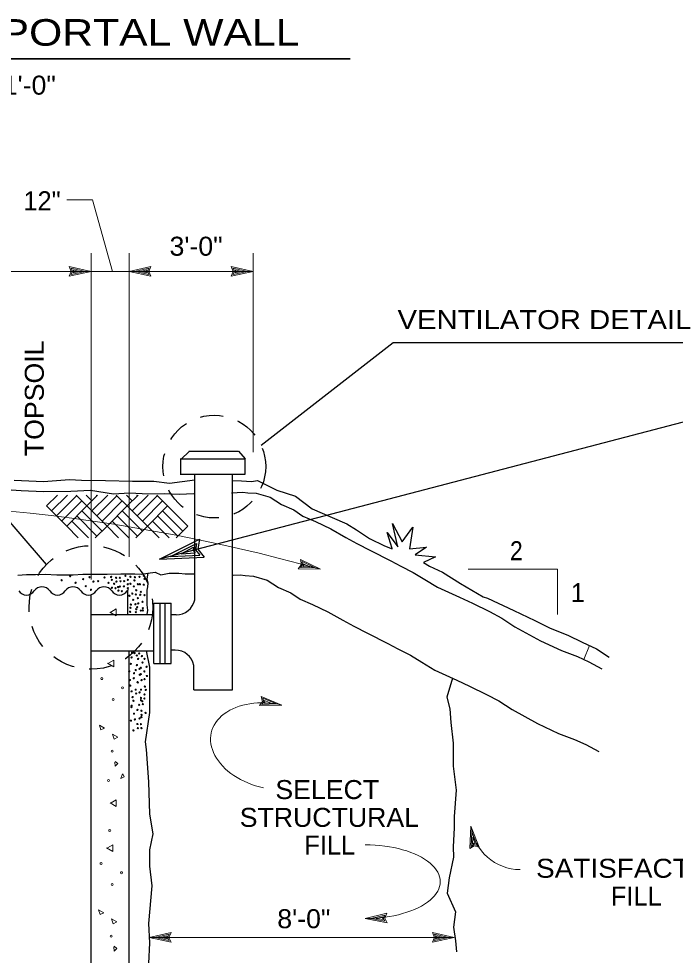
# Model space of a CAD drawing. Extents: x -22.3 to 19.7, y -11.8 to 18.2.
# Drawn here: x -4.47 to -0.15, y -6.32 to -0.16 of the extents above; entities that cross this region are included whole.
import ezdxf
from ezdxf.enums import TextEntityAlignment as Align

# ---------------------------------------------------------------- set-up
doc = ezdxf.new("R2010")
doc.units = 0
doc.header["$LTSCALE"] = 0.05
doc.linetypes.add('MEDIUM_DASHED', pattern=[4.5, 3, -1.5])
doc.layers.add('1', color=7, linetype='Continuous', lineweight=13)
doc.layers.add('2', color=7, linetype='Continuous', lineweight=13)

msp = doc.modelspace()

# ---------------------------------------------------------------- linework, layer by layer
at = {"layer": '1', "lineweight": 35}
msp.add_line((-7.37642, -0.42569), (-2.28642, -0.42569), dxfattribs=at)
at = {"layer": '1'}
for p, q in [((-3.99142, -3.85069), (-3.99142, -1.70369)), ((-3.74142, -3.70269), (-3.74142, -1.70369)), ((-2.92542, -3.01369), (-2.92542, -1.70369)), ((-8.41542, -1.82369), (-3.99142, -1.82369)), ((-3.99142, -1.82369), (-4.13542, -1.79269)), ((-3.99142, -1.82369), (-4.13542, -1.85469)), ((-4.02842, -1.82369), (-4.12242, -1.80369)), ((-4.11342, -1.82369), (-4.12242, -1.80369)), ((-4.02842, -1.82369), (-4.12242, -1.84369)), ((-4.12242, -1.84369), (-4.11342, -1.82369)), ((-4.06442, -1.82369), (-4.10942, -1.81469)), ((-4.10542, -1.82369), (-4.10942, -1.81469)), ((-4.06442, -1.82369), (-4.10942, -1.83369)), ((-4.10942, -1.83369), (-4.10542, -1.82369)), ((-3.74142, -1.82369), (-3.59742, -1.79269)), ((-3.74142, -1.82369), (-3.59742, -1.85469)), ((-3.70442, -1.82369), (-3.61042, -1.80369)), ((-3.70442, -1.82369), (-3.61042, -1.84369)), ((-3.66842, -1.82369), (-3.62342, -1.81369)), ((-3.66842, -1.82369), (-3.62342, -1.83269)), ((-3.62342, -1.81369), (-3.62742, -1.82369)), ((-3.62742, -1.82369), (-3.62342, -1.83269)), ((-3.61042, -1.80369), (-3.61942, -1.82369)), ((-3.61942, -1.82369), (-3.61042, -1.84369)), ((-2.92542, -1.82369), (-3.06942, -1.79269)), ((-2.92542, -1.82369), (-3.06942, -1.85469)), ((-2.96242, -1.82369), (-3.05642, -1.80369)), ((-3.04742, -1.82369), (-3.05642, -1.80369)), ((-2.96242, -1.82369), (-3.05642, -1.84369)), ((-3.05642, -1.84369), (-3.04742, -1.82369)), ((-2.99842, -1.82369), (-3.04342, -1.81469)), ((-3.03942, -1.82369), (-3.04342, -1.81469)), ((-2.99842, -1.82369), (-3.04342, -1.83369)), ((-3.04342, -1.83369), (-3.03942, -1.82369)), ((-4.28442, -3.36669), (-4.21342, -3.29569)), ((-4.25142, -3.40069), (-4.14742, -3.29569)), ((-4.21842, -3.43369), (-4.08542, -3.29969)), ((-4.01942, -3.36669), (-4.09042, -3.29569)), ((-3.98642, -3.33369), (-4.02442, -3.29569)), ((-4.01942, -3.36669), (-3.94842, -3.29569)), ((-4.01942, -3.36669), (-3.94842, -3.29569)), ((-3.98642, -3.40069), (-3.88142, -3.29569)), ((-3.95342, -3.29969), (-3.95742, -3.29569)), ((-3.95342, -3.43369), (-3.82042, -3.29969)), ((-3.75342, -3.36669), (-3.82542, -3.29569)), ((-3.72042, -3.33369), (-3.75842, -3.29569)), ((-3.75342, -3.36669), (-3.68242, -3.29569)), ((-3.72042, -3.40069), (-3.61542, -3.29569)), ((-3.68742, -3.29969), (-3.69142, -3.29569)), ((-3.68742, -3.43369), (-3.55442, -3.29969)), ((-3.48842, -3.36669), (-3.55942, -3.29569)), ((-4.18542, -3.46669), (-4.05242, -3.33369)), ((-4.15142, -3.49969), (-4.01942, -3.36669)), ((-3.88642, -3.49969), (-4.01942, -3.36669)), ((-3.91942, -3.46669), (-3.78742, -3.33369)), ((-3.88642, -3.49969), (-3.75342, -3.36669)), ((-3.65342, -3.46669), (-3.52142, -3.33369)), ((-3.62042, -3.49969), (-3.48842, -3.36669)), ((-3.35542, -3.49969), (-3.48842, -3.36669)), ((-3.95342, -3.56569), (-4.08542, -3.43369)), ((-3.91942, -3.53269), (-4.05242, -3.40069)), ((-3.68642, -3.56569), (-3.82042, -3.43369)), ((-3.65342, -3.53269), (-3.78742, -3.40069)), ((-3.42142, -3.56569), (-3.55442, -3.43369)), ((-3.38842, -3.53269), (-3.52142, -3.40069)), ((-4.00942, -3.57669), (-4.11842, -3.46669)), ((-3.96342, -3.57669), (-3.88642, -3.49969)), ((-3.81042, -3.57669), (-3.88642, -3.49969)), ((-3.74242, -3.57669), (-3.85342, -3.46669)), ((-3.69742, -3.57669), (-3.62042, -3.49969)), ((-3.47742, -3.57669), (-3.58742, -3.46669)), ((-3.43242, -3.57669), (-3.35542, -3.49969)), ((-2.48142, -3.78469), (-2.61342, -3.72069)), ((-2.61342, -3.77269), (-2.59942, -3.75569)), ((-2.51742, -3.77569), (-2.60342, -3.73369)), ((-2.59942, -3.75569), (-2.60342, -3.73369)), ((-2.59842, -3.76669), (-2.59242, -3.75769)), ((-2.55242, -3.76769), (-2.59342, -3.74769)), ((-2.59242, -3.75769), (-2.59342, -3.74769)), ((-2.48142, -3.78469), (-2.62842, -3.78069)), ((-2.51742, -3.77569), (-2.61342, -3.77269)), ((-2.55242, -3.76769), (-2.59842, -3.76669)), ((-0.74842, -4.37869), (-0.71142, -4.28669)), ((-2.73542, -4.67769), (-2.87142, -4.62069)), ((-2.73542, -4.67769), (-2.88242, -4.68169)), ((-2.86742, -4.67369), (-2.85542, -4.65569)), ((-2.77142, -4.67069), (-2.86742, -4.67369)), ((-2.77142, -4.67069), (-2.86042, -4.63369)), ((-2.85542, -4.65569), (-2.86042, -4.63369)), ((-2.85342, -4.66569), (-2.84742, -4.65669)), ((-2.80742, -4.66469), (-2.85342, -4.66569)), ((-2.80742, -4.66469), (-2.84942, -4.64769)), ((-2.84742, -4.65669), (-2.84942, -4.64769)), ((-1.49242, -5.47569), (-1.49942, -5.62269)), ((-1.49242, -5.47569), (-1.43842, -5.61269)), ((-1.48642, -5.51169), (-1.49042, -5.60869)), ((-1.48642, -5.51169), (-1.45142, -5.60169)), ((-1.47242, -5.59569), (-1.49042, -5.60869)), ((-1.48042, -5.54769), (-1.48142, -5.59369)), ((-1.47342, -5.58769), (-1.48142, -5.59369)), ((-1.48042, -5.54769), (-1.46342, -5.59069)), ((-1.46342, -5.59069), (-1.47342, -5.58769)), ((-1.45142, -5.60169), (-1.47242, -5.59569)), ((-2.18842, -6.08269), (-2.04542, -6.04869)), ((-2.18842, -6.08269), (-2.04342, -6.11069)), ((-2.15142, -6.08169), (-2.05742, -6.05969)), ((-2.15142, -6.08169), (-2.05742, -6.09969)), ((-2.11542, -6.08169), (-2.07042, -6.07069)), ((-2.11542, -6.08169), (-2.07042, -6.08969)), ((-2.07042, -6.07069), (-2.07442, -6.08069)), ((-2.07442, -6.08069), (-2.07042, -6.08969)), ((-2.05742, -6.05969), (-2.06642, -6.08069)), ((-2.06642, -6.08069), (-2.05742, -6.09969)), ((-3.60942, -6.20669), (-3.46542, -6.17569)), ((-3.60942, -6.20669), (-1.60142, -6.20669)), ((-3.60942, -6.20669), (-3.46542, -6.23769)), ((-3.57242, -6.20669), (-3.47842, -6.18669)), ((-3.57242, -6.20669), (-3.47842, -6.22669)), ((-3.53642, -6.20669), (-3.49142, -6.19669)), ((-3.53642, -6.20669), (-3.49142, -6.21569)), ((-3.49142, -6.19669), (-3.49542, -6.20669)), ((-3.49542, -6.20669), (-3.49142, -6.21569)), ((-3.47842, -6.18669), (-3.48742, -6.20669)), ((-3.48742, -6.20669), (-3.47842, -6.22669)), ((-1.60142, -6.20669), (-1.74542, -6.17569)), ((-1.60142, -6.20669), (-1.74542, -6.23769)), ((-1.63842, -6.20669), (-1.73242, -6.18669)), ((-1.72342, -6.20669), (-1.73242, -6.18669)), ((-1.63842, -6.20669), (-1.73242, -6.22669)), ((-1.73242, -6.22669), (-1.72342, -6.20669)), ((-1.67442, -6.20669), (-1.71942, -6.19769)), ((-1.71542, -6.20669), (-1.71942, -6.19769)), ((-1.67442, -6.20669), (-1.71942, -6.21669)), ((-1.71942, -6.21669), (-1.71542, -6.20669))]:
    msp.add_line(p, q, dxfattribs=at)
at = {"layer": '1', "lineweight": 25}
for p, q in [((-2.00442, -2.29469), (-2.87242, -2.96869)), ((-0.01042, -2.29469), (-2.00442, -2.29469)), ((-3.40142, -3.06269), (-3.34442, -3.00669)), ((-3.34842, -3.00669), (-3.02142, -3.00669)), ((-3.02142, -3.00669), (-2.97742, -3.05769)), ((-3.40542, -3.05769), (-2.97742, -3.05769)), ((-3.40142, -3.16369), (-3.40142, -3.06269)), ((-2.97742, -3.15869), (-2.97742, -3.05769)), ((-3.40242, -3.15869), (-2.97742, -3.15869)), ((-3.30942, -3.98469), (-3.30942, -3.16169)), ((-3.06142, -4.57769), (-3.06142, -3.15869)), ((-3.46842, -3.69969), (-3.29742, -3.61369)), ((-3.29742, -3.61369), (-3.30442, -3.65669)), ((-3.46842, -3.69969), (-3.27642, -3.69069)), ((-3.39942, -3.68169), (-3.31742, -3.63969)), ((-3.39942, -3.68169), (-3.30742, -3.67669)), ((-3.31742, -3.63969), (-3.31942, -3.66069)), ((-3.31942, -3.66069), (-3.30742, -3.67669)), ((-3.30442, -3.65669), (-3.27642, -3.69069)), ((-3.54042, -3.71869), (-3.24642, -3.70569)), ((-3.75042, -4.08169), (-3.75042, -3.91869)), ((-3.99142, -7.93169), (-3.99142, -3.95369)), ((-3.57942, -4.40369), (-3.57942, -4.00769)), ((-3.57942, -4.00769), (-3.46542, -4.00769)), ((-3.53742, -4.40369), (-3.53742, -4.00769)), ((-3.50442, -4.40369), (-3.50442, -4.00769)), ((-3.46542, -4.40369), (-3.46542, -4.00769)), ((-3.99142, -4.08169), (-3.57942, -4.08169)), ((-3.43242, -4.08469), (-3.46542, -4.08469)), ((-3.99142, -4.32169), (-3.57942, -4.32169)), ((-3.74142, -7.93169), (-3.74142, -4.32169)), ((-3.43742, -4.31669), (-3.46542, -4.31669)), ((-3.57942, -4.40369), (-3.46542, -4.40369)), ((-3.31442, -4.57769), (-3.31442, -4.41669)), ((-3.31442, -4.57769), (-3.06142, -4.57769))]:
    msp.add_line(p, q, dxfattribs=at)
at = {"layer": '1'}
for points in [[(-3.85142, -1.82369), (-3.98242, -1.35269), (-4.15142, -1.35269)], [(-4.13542, -1.85469), (-4.12142, -1.82369), (-4.13542, -1.79269)], [(-3.99142, -1.82369), (-3.74142, -1.82369), (-2.92542, -1.82369)], [(-3.59742, -1.79269), (-3.61142, -1.82369), (-3.59742, -1.85469)], [(-3.06942, -1.85469), (-3.05542, -1.82369), (-3.06942, -1.79269)], [(-3.54442, -3.57669), (-3.75342, -3.36669), (-3.68242, -3.29569)], [(-4.07542, -3.57669), (-4.15142, -3.49969), (-4.28442, -3.36669)], [(-2.62842, -3.78069), (-2.60742, -3.75369), (-2.61342, -3.72069)], [(-1.50942, -3.78469), (-0.92142, -3.78469), (-0.92142, -4.08269)], [(-2.88242, -4.68169), (-2.86342, -4.65369), (-2.87142, -4.62069)], [(-1.43842, -5.61269), (-1.47142, -5.60369), (-1.49942, -5.62269)], [(-2.04542, -6.04869), (-2.05842, -6.08069), (-2.04342, -6.11069)], [(-3.46542, -6.17569), (-3.47942, -6.20669), (-3.46542, -6.23769)], [(-1.74542, -6.23769), (-1.73142, -6.20669), (-1.74542, -6.17569)]]:
    msp.add_lwpolyline(points, dxfattribs=at)
at = {"layer": '1', "lineweight": 25}
for points in [[(-6.26642, -2.32569), (-5.51542, -2.32569), (-4.28642, -3.75369)], [(1.92558, -2.28769), (-3.54042, -3.71869), (-3.27742, -3.58569)], [(-4.49642, -3.19769), (-4.30442, -3.20569), (-4.13442, -3.19369), (-4.05342, -3.19869), (-3.89642, -3.20069), (-3.71942, -3.20369), (-3.57842, -3.20369), (-3.47642, -3.21669), (-3.30942, -3.19569)], [(-3.06042, -3.19969), (-3.00242, -3.20169), (-2.93542, -3.20669), (-2.89642, -3.20069), (-2.76942, -3.26269), (-2.64542, -3.30369), (-2.53742, -3.38569), (-2.40442, -3.44469), (-2.30942, -3.48569), (-2.24542, -3.52569), (-2.15942, -3.58269), (-2.06142, -3.62969), (-2.01042, -3.64969), (-2.01042, -3.64869), (-2.04342, -3.54269), (-1.97342, -3.63669), (-2.00842, -3.48369), (-1.94542, -3.60269), (-1.87442, -3.50669), (-1.89642, -3.65069), (-1.78342, -3.63969), (-1.85842, -3.68969), (-1.72542, -3.70269), (-1.80442, -3.73869), (-1.76442, -3.76369), (-1.67942, -3.80269), (-1.56042, -3.87869), (-1.41142, -3.96469), (-1.38342, -3.97469), (-1.21042, -4.05569), (-1.07242, -4.12169), (-0.97142, -4.17169), (-0.85442, -4.21869), (-0.75942, -4.26469), (-0.66642, -4.30769), (-0.58242, -4.36369)], [(-7.18642, -3.26769), (-6.94542, -3.26969), (-6.68842, -3.26469), (-6.47842, -3.26069), (-6.30242, -3.27369), (-6.14842, -3.27069), (-5.85542, -3.27169), (-5.57142, -3.26469), (-5.41742, -3.26569), (-5.22942, -3.26569), (-5.00642, -3.25869), (-4.78642, -3.24969), (-4.61642, -3.25469), (-4.45142, -3.26569), (-4.30442, -3.27269), (-4.12542, -3.27069), (-3.99542, -3.26469), (-3.84342, -3.28769), (-3.73842, -3.28069), (-3.61442, -3.28869), (-3.50942, -3.28469), (-3.41242, -3.29069), (-3.31442, -3.28569)], [(-3.06742, -3.28069), (-2.99242, -3.27669), (-2.95942, -3.28069), (-2.90442, -3.28369), (-2.81342, -3.31069), (-2.73842, -3.35869), (-2.65742, -3.39369), (-2.59742, -3.43569), (-2.51542, -3.47069), (-2.41342, -3.51869), (-2.31542, -3.57469), (-2.24242, -3.61469), (-2.15242, -3.66069), (-2.01942, -3.72869), (-1.95342, -3.76369), (-1.87142, -3.80469), (-1.79542, -3.85169), (-1.71142, -3.90269), (-1.56642, -3.96869), (-1.48142, -4.00769), (-1.36942, -4.06269), (-1.28942, -4.10569), (-1.20242, -4.16269), (-1.03442, -4.25469), (-0.89642, -4.31969), (-0.79142, -4.35869), (-0.71642, -4.39269), (-0.63142, -4.43869)], [(-3.27742, -3.58569), (-3.28842, -3.65269), (-3.24642, -3.70569)], [(-4.47242, -3.82369), (-4.41542, -3.81869), (-4.35642, -3.81869), (-4.29242, -3.81569), (-4.21742, -3.82069), (-4.17342, -3.82069), (-4.10942, -3.82069), (-4.04542, -3.81569), (-3.96642, -3.81569), (-3.88542, -3.81569), (-3.79642, -3.81369), (-3.70342, -3.81369), (-3.65742, -3.81569), (-3.61842, -3.80969), (-3.62342, -3.84769), (-3.61842, -3.87369), (-3.61942, -3.90069), (-3.62342, -3.92169), (-3.62342, -3.96969), (-3.62342, -4.00769), (-3.62542, -4.01769), (-3.61942, -4.05369), (-3.62342, -4.08169)], [(-3.61842, -3.80969), (-3.57042, -3.80369), (-3.53142, -3.82169), (-3.47742, -3.81069), (-3.41342, -3.81069), (-3.37142, -3.81469), (-3.30942, -3.81469)], [(-3.05742, -3.82369), (-3.01142, -3.82169), (-2.97842, -3.82569), (-2.92342, -3.82869), (-2.83242, -3.85569), (-2.75742, -3.90369), (-2.67642, -3.93869), (-2.61642, -3.98069), (-2.53442, -4.01569), (-2.43242, -4.06369), (-2.33442, -4.11969), (-2.26142, -4.15969), (-2.17142, -4.20569), (-2.03842, -4.27369), (-1.97242, -4.30869), (-1.89042, -4.34969), (-1.81442, -4.39669), (-1.73042, -4.44769), (-1.58542, -4.51369), (-1.50042, -4.55269), (-1.38842, -4.60769), (-1.30842, -4.65069), (-1.22142, -4.70769), (-1.05342, -4.79969), (-0.91542, -4.86469), (-0.81042, -4.90369), (-0.73542, -4.93769), (-0.65042, -4.98369)], [(-3.62842, -4.32169), (-3.60742, -4.42869), (-3.60742, -4.52069), (-3.60742, -4.62769), (-3.60742, -4.72769), (-3.63542, -4.91969), (-3.62842, -4.96969), (-3.61442, -5.18269), (-3.60742, -5.39669), (-3.58542, -5.52469), (-3.60742, -5.63169), (-3.60742, -5.73869), (-3.59242, -5.86669), (-3.61442, -6.11569), (-3.60742, -6.24369), (-3.61442, -6.37869)], [(-1.61342, -4.50069), (-1.65042, -4.62669), (-1.63042, -4.70269), (-1.62342, -4.79169), (-1.60942, -4.92969), (-1.60942, -5.08069), (-1.58842, -5.23869), (-1.60242, -5.41069), (-1.60242, -5.48669), (-1.60942, -5.61069)], [(-1.60942, -5.61069), (-1.60742, -5.67969), (-1.63442, -5.81469), (-1.64842, -5.91669), (-1.59342, -6.03869), (-1.60742, -6.13969), (-1.59342, -6.22869), (-1.58742, -6.30269)]]:
    msp.add_lwpolyline(points, dxfattribs=at)
at = {"layer": '1', "linetype": 'MEDIUM_DASHED', "lineweight": 25}
for centre, radius in [((-3.18042, -3.10869), 0.338), ((-3.99242, -4.03569), 0.40702)]:
    msp.add_circle(centre, radius, dxfattribs=at)
at = {"layer": '1'}
for centre in [(-4.18492, -3.85669), (-4.12892, -3.83069), (-4.09292, -3.87269), (-4.04392, -3.84969), (-4.00192, -3.83669), (-3.97592, -3.86569), (-3.94492, -3.86269), (-3.90292, -3.83769), (-3.87692, -3.87369), (-3.85992, -3.83469), (-3.85392, -3.85369), (-3.83992, -3.87969), (-3.82692, -3.83969), (-3.82492, -3.86569), (-3.80192, -3.83969), (-3.79792, -3.86369), (-3.77292, -3.86269), (-3.76592, -3.82769), (-3.74992, -3.88269), (-3.74892, -3.85369), (-3.73292, -3.83369), (-3.73292, -3.87969), (-3.70592, -3.85769), (-3.70292, -3.83669), (-3.68292, -3.88269), (-3.67292, -3.83469), (-3.66992, -3.88269), (-3.64492, -3.82769), (-3.64492, -3.88569), (-3.63992, -3.84669), (-4.02692, -3.89569), (-3.99192, -3.91869), (-3.85392, -3.90569), (-3.83092, -3.90969), (-3.81392, -3.90169), (-3.81192, -3.92469), (-3.80192, -3.89869), (-3.78892, -3.92869), (-3.77492, -3.89669), (-3.74992, -3.90869), (-3.71992, -3.94469), (-3.70992, -3.89669), (-3.69392, -3.92269), (-3.66392, -3.93269), (-3.73892, -3.95869), (-3.71392, -3.98569), (-3.69692, -3.94969), (-3.68292, -3.97469), (-3.68092, -4.00869), (-3.66792, -3.95169), (-3.65292, -3.99769), (-3.63992, -3.95469), (-3.73492, -4.06369), (-3.73292, -4.03769), (-3.72892, -4.01669), (-3.69992, -4.01469), (-3.69692, -4.06669), (-3.69392, -4.04769), (-3.68892, -4.03369), (-3.66392, -4.05669), (-3.65092, -4.04069), (-3.65092, -4.05469), (-3.72492, -4.36469), (-3.72192, -4.33369), (-3.70492, -4.33569), (-3.69092, -4.35169), (-3.68192, -4.37469), (-3.67492, -4.33769), (-3.65692, -4.35569), (-3.63992, -4.37469), (-3.72892, -4.40669), (-3.68992, -4.41469), (-3.67192, -4.43969), (-3.66392, -4.43269), (-3.65292, -4.39869), (-3.62592, -4.42569), (-3.73992, -4.45669), (-3.71092, -4.50169), (-3.70892, -4.46869), (-3.69792, -4.44769), (-3.67092, -4.47869), (-3.66292, -4.47469), (-3.64092, -4.45669), (-3.62392, -4.48669), (-3.73592, -4.51369), (-3.73392, -4.54969), (-3.68592, -4.52669), (-3.68392, -4.52969), (-3.65892, -4.51369), (-3.63992, -4.50669), (-3.63692, -4.55669), (-3.72492, -4.58769), (-3.71792, -4.62569), (-3.69792, -4.57669), (-3.69492, -4.60169), (-3.67192, -4.59469), (-3.66292, -4.57669), (-3.63992, -4.60769), (-3.63192, -4.57869), (-3.72492, -4.68269), (-3.71292, -4.64969), (-3.67492, -4.67669), (-3.66292, -4.63069), (-3.66292, -4.64569), (-3.65492, -4.65269), (-3.65092, -4.67169), (-3.64092, -4.63469), (-3.72592, -4.69169), (-3.70892, -4.73469), (-3.68692, -4.70969), (-3.65992, -4.71569), (-3.65892, -4.74269), (-3.63292, -4.72969), (-3.72892, -4.78069), (-3.70292, -4.77269), (-3.68692, -4.80269), (-3.67192, -4.76569), (-3.66292, -4.80369), (-3.65992, -4.75669), (-3.71292, -4.84469), (-3.68392, -4.82969), (-3.65992, -4.82969)]:
    msp.add_circle(centre, 0.0043, dxfattribs=at)
for centre, radius, start, end in [((-5.65272, -15.07871), 11.73082, 74.31555, 96.07119), ((-1.16652, -5.43185), 0.32884, 187.66046, 269.843)]:
    msp.add_arc(centre, radius, start, end, dxfattribs=at)
at = {"layer": '1', "lineweight": 25}
for centre, radius, start, end in [((-4.41642, -3.89219), 0.06157, 214.0772, 325.92281), ((-4.31442, -3.96119), 0.06157, 34.0772, 145.92281), ((-4.21242, -3.89219), 0.06157, 214.0772, 325.92281), ((-4.11042, -3.96119), 0.06157, 34.0772, 145.92281), ((-4.00842, -3.89219), 0.06157, 214.0772, 325.92281), ((-3.90642, -3.96119), 0.06157, 34.0772, 145.92281), ((-3.80442, -3.89219), 0.06157, 214.0772, 325.92281), ((-3.70242, -3.96119), 0.06157, 135.33506, 145.92281), ((-3.43243, -3.95903), 0.12566, 270.00597, 348.21682), ((-3.43743, -4.44235), 0.12566, 11.78318, 89.99403)]:
    msp.add_arc(centre, radius, start, end, dxfattribs=at)
at = {"layer": '1'}
for centre, major_axis, ratio in [((-2.79642, -4.95069), (0.40413, -0.0903), 0.675521), ((-2.18842, -5.84019), (-0.49458, 0), 0.490314)]:
    msp.add_ellipse(centre, major_axis=major_axis, ratio=ratio, start_param=1.5707963, end_param=4.712389, dxfattribs=at)
at = {"layer": '2'}
for points in [[(-3.86042, -4.06569), (-3.82642, -4.04569), (-3.82642, -4.08969), (-3.86742, -4.06569)], [(-3.87642, -4.40269), (-3.84242, -4.38269), (-3.84242, -4.42669), (-3.88342, -4.40269)], [(-3.83242, -5.04969), (-3.81542, -5.06369), (-3.83242, -5.08069), (-3.83542, -5.05369)], [(-3.78142, -5.13069), (-3.77442, -5.15069), (-3.79542, -5.16069), (-3.78542, -5.13069)], [(-3.85942, -5.32169), (-3.82542, -5.30169), (-3.82542, -5.34569), (-3.86642, -5.32169)], [(-3.88242, -5.61869), (-3.84842, -5.59869), (-3.84842, -5.64269), (-3.88942, -5.61869)], [(-3.83842, -6.26569), (-3.82142, -6.27969), (-3.83842, -6.29669), (-3.84142, -6.26969)]]:
    msp.add_lwpolyline(points, dxfattribs=at)
for points in [[(-3.93642, -4.80969), (-3.90242, -4.82969), (-3.92642, -4.84069)], [(-3.85042, -4.86969), (-3.81642, -4.88969), (-3.84042, -4.90169)], [(-3.94242, -6.02569), (-3.90842, -6.04569), (-3.93242, -6.05669)], [(-3.85642, -6.08569), (-3.82242, -6.10569), (-3.84642, -6.11769)]]:
    msp.add_lwpolyline(points, close=True, dxfattribs=at)
for centre in [(-3.91992, -4.50419), (-3.78492, -4.56519), (-3.84592, -4.64219), (-3.85292, -4.98219), (-3.87592, -5.17419), (-3.86892, -5.50419), (-3.92592, -5.72019), (-3.79092, -5.78119), (-3.85192, -5.85819), (-3.85892, -6.19819)]:
    msp.add_circle(centre, 0.0065, dxfattribs=at)

# ---------------------------------------------------------------- texts
at = {"layer": '1'}
for s, height, width, p in [('PARTIAL PLAN - PORTAL WALL', 0.175, 1.2, (-4.71942, -0.33869)), ('SCALE: 1/4"=1\'-0"', 0.125, 1.05, (-4.93892, -0.66069)), ('3\'-0"', 0.125, 1.05, (-3.30042, -1.72069)), ('2', 0.125, 0.9, (-1.19292, -3.72469)), ('SELECT', 0.125, 1.05, (-2.43742, -5.29669)), ('STRUCTURAL', 0.125, 1.05, (-2.42342, -5.47969)), ('SATISFACTORY', 0.125, 1.1, (-0.35842, -5.81469)), ('8\'-0"', 0.125, 1.05, (-2.59142, -6.14669))]:
    msp.add_text(s, height=height, dxfattribs=dict(at, width=width)).set_placement(p, align=Align.CENTER)
msp.add_text('12"', height=0.125, dxfattribs=at).set_placement((-4.19142, -1.42169), align=Align.RIGHT)
at = {"layer": '1', "width": 1.15}
msp.add_text('VENTILATOR DETAIL', height=0.125, dxfattribs=at).set_placement((-0.04142, -2.20369), align=Align.RIGHT)
at = {"layer": '1', "width": 1.05}
msp.add_text('TOPSOIL', height=0.125, rotation=90, dxfattribs=at).set_placement((-4.30242, -3.03969))
at = {"layer": '1'}
for s, p in [('1', (-0.78853, -4.00069)), ('FILL', (-2.42092, -5.66169)), ('FILL', (-0.40392, -5.99769))]:
    msp.add_text(s, height=0.125, dxfattribs=at).set_placement(p, align=Align.CENTER)

doc.saveas('drawing.dxf')
